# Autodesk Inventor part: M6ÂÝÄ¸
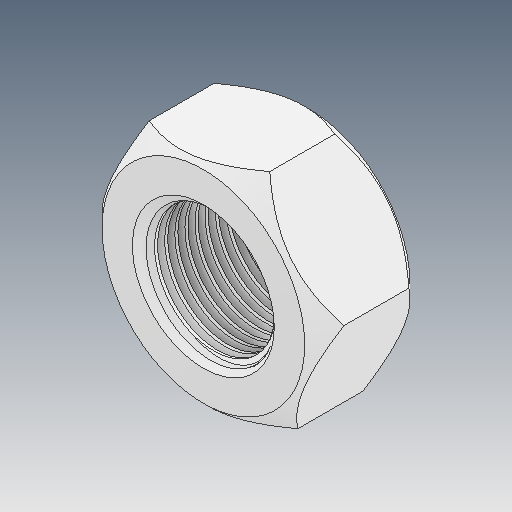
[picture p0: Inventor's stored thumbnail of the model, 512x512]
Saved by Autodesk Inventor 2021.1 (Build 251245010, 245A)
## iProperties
Created: 2021-06
Part Number: M6ÂÝÄ¸
Material: Ogólny
Document SubType Name: Modeling
Designer: user
Density: 1 g/cm^3
Appearance: Domyślna
Author: user
Revision Number: ÈÎºÎ
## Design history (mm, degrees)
feature "ÇÐ³ý-É¨Ãè1"
node "Bryła1"
